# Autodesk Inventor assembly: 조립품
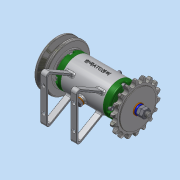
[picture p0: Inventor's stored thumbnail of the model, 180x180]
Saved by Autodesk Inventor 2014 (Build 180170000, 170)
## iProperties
Created: 2016-03
Part Number: 조립품
Document SubType Name: Assembly
Designer: 406-9
Author: 406-9
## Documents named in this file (16)
- C:\Users\406-9\Desktop\조립품.iam
- C:\Users\406-9\Desktop\부품1.ipt
- C:\Users\406-9\Desktop\베어링 15 x 32 x 9.ipt
- C:\Users\406-9\Desktop\축.ipt
- C:\Users\406-9\Desktop\키 3 x 3 x 12.ipt
- C:\Users\406-9\Desktop\커버.ipt
- C:\Users\406-9\Desktop\V벨트풀리.ipt
- C:\Users\406-9\Desktop\스프로킷.ipt
- C:\Users\406-9\Desktop\너트 M 8.ipt
- C:\Users\406-9\Desktop\스프링와셔 8.ipt
- C:\Users\406-9\Desktop\와셔 8x17.ipt
- C:\Users\406-9\Desktop\볼트 M 6 x 8.ipt
- C:\Users\406-9\Desktop\와셔 6x11.5.ipt
- C:\Users\406-9\Desktop\니플 M 6 x 0.75.ipt
- C:\Users\406-9\Desktop\볼트 M4 x 12.ipt
- C:\Users\406-9\Desktop\오일 실 15 25 7.ipt
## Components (11 placed, 3 different names)
1. KS B 2023 6002 - 15 x 32 x 9:1
2. KS B 2023 6002 - 15 x 32 x 9:2
3. V벨트풀리:1 — 각도:3
4. ISO 4762 M4 x 12:1
5. ISO 4762 M4 x 12:2
6. ISO 4762 M4 x 12:3
7. ISO 4762 M4 x 12:4
8. ISO 4762 M4 x 12:5
9. ISO 4762 M4 x 12:6
10. ISO 4762 M4 x 12:7
11. ISO 4762 M4 x 12:8
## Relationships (1: Angle 1)
- 각도:3 [Angle]: V벨트풀리:1
